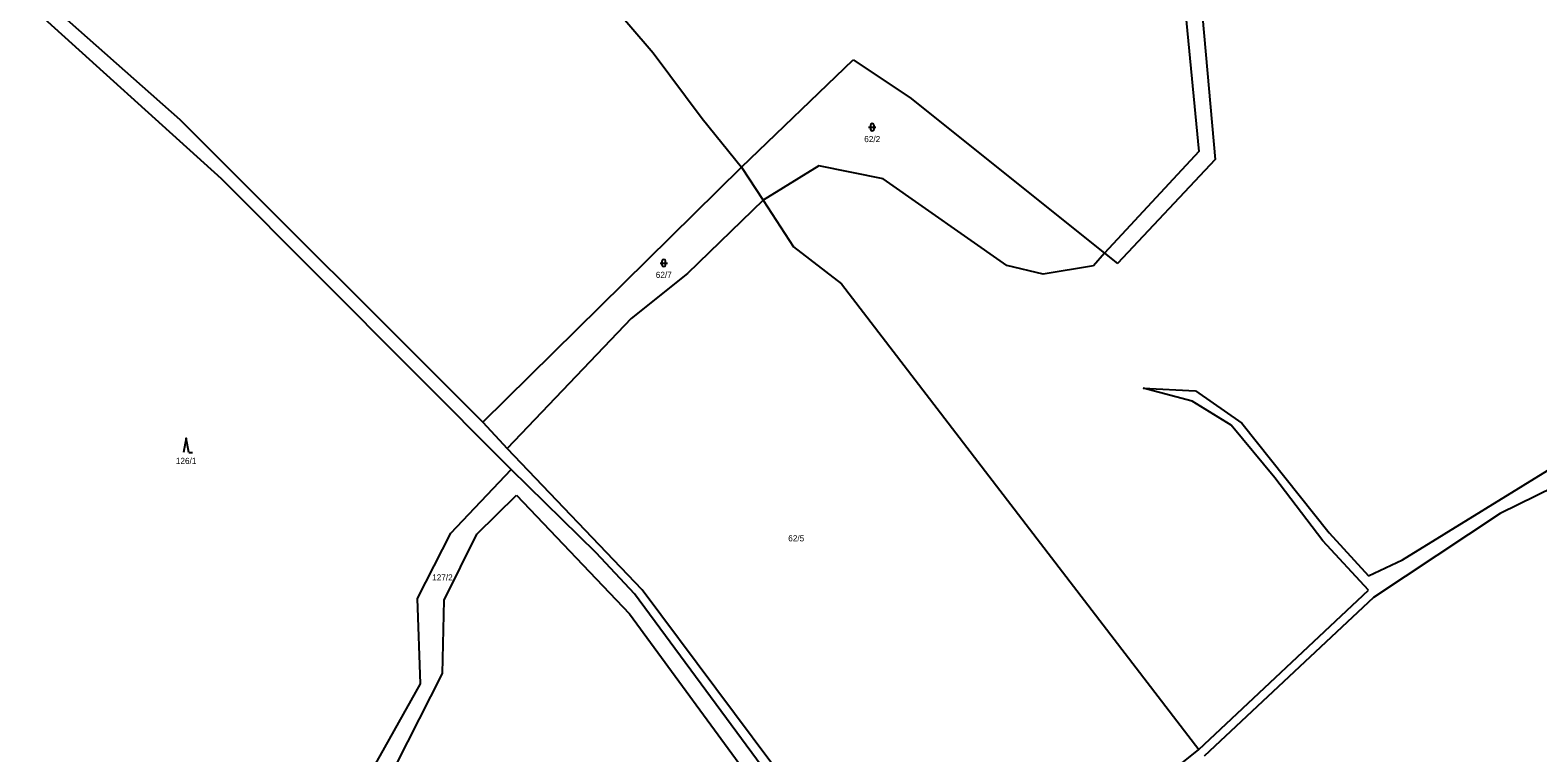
# Model space of a CAD drawing. Extents: x -601877 to -599786, y -1122905 to -1121218.
# Drawn here: x -600624.1 to -600206.4, y -1122172.1 to -1121972.1 of the extents above; entities that cross this region are included whole.
import ezdxf
from ezdxf.enums import TextEntityAlignment as Align

# ---------------------------------------------------------------- set-up
doc = ezdxf.new("R2010")
doc.units = 0
doc.header["$LTSCALE"] = 0.68
doc.layers.add('1', color=7, linetype='Continuous', lineweight=25)
doc.layers.add('3', color=7, linetype='Continuous', lineweight=25)
doc.layers.add('2', color=7, linetype='Continuous')

msp = doc.modelspace()

# ---------------------------------------------------------------- linework, layer by layer
at = {"layer": '1'}
for p, q in [((-600481.34, -1121943.53), (-600451.53, -1121978.39)), ((-600621.15, -1121962.72), (-600582.62, -1121996.8)), ((-600624.09, -1121965.36), (-600571.21, -1122013.14)), ((-600304.07, -1121967.38), (-600300.36, -1122005.74)), ((-600299.3, -1121968.61), (-600295.78, -1122007.91)), ((-600451.53, -1121978.39), (-600437.92, -1121996.56)), ((-600427, -1122010.05), (-600396.05, -1121980.36)), ((-600396.05, -1121980.36), (-600380.36, -1121990.79)), ((-600380.36, -1121990.79), (-600326.42, -1122033.8)), ((-600582.62, -1121996.8), (-600498.69, -1122080.61)), ((-600437.92, -1121996.56), (-600427, -1122010.05)), ((-600300.36, -1122005.74), (-600326.42, -1122033.8)), ((-600295.78, -1122007.91), (-600322.82, -1122036.66)), ((-600498.69, -1122080.61), (-600427, -1122010.05)), ((-600427, -1122010.05), (-600421.06, -1122019.14)), ((-600405.63, -1122009.69), (-600421.06, -1122019.14)), ((-600387.78, -1122013.29), (-600405.63, -1122009.69)), ((-600571.21, -1122013.14), (-600490.88, -1122093.71)), ((-600353.56, -1122037.22), (-600387.78, -1122013.29)), ((-600421.06, -1122019.14), (-600441.98, -1122039.43)), ((-600421.06, -1122019.14), (-600412.62, -1122032.05)), ((-600412.62, -1122032.05), (-600399.28, -1122042.29)), ((-600343.49, -1122039.68), (-600353.56, -1122037.22)), ((-600329.49, -1122037.3), (-600343.49, -1122039.68)), ((-600326.42, -1122033.8), (-600329.49, -1122037.3)), ((-600326.42, -1122033.8), (-600322.82, -1122036.66)), ((-600441.98, -1122039.43), (-600457.62, -1122051.88)), ((-600399.28, -1122042.29), (-600300.33, -1122171.21)), ((-600457.62, -1122051.88), (-600491.92, -1122087.9)), ((-600302.16, -1122074.84), (-600315.76, -1122071.21)), ((-600315.76, -1122071.21), (-600301.24, -1122071.92)), ((-600291.38, -1122081.42), (-600302.16, -1122074.84)), ((-600301.24, -1122071.92), (-600288.45, -1122080.88)), ((-600498.69, -1122080.61), (-600491.92, -1122087.9)), ((-600279.32, -1122096.05), (-600291.38, -1122081.42)), ((-600288.45, -1122080.88), (-600264.24, -1122111.23)), ((-600454.5, -1122127.05), (-600491.92, -1122087.9)), ((-600179.54, -1122087.46), (-600216.82, -1122105.93)), ((-600243.87, -1122118.73), (-600198.91, -1122091.02)), ((-600507.55, -1122111.3), (-600490.88, -1122093.71)), ((-600467.31, -1122116.76), (-600490.88, -1122093.71)), ((-600265.98, -1122113.42), (-600279.32, -1122096.05)), ((-600500.31, -1122111.64), (-600489.36, -1122100.86)), ((-600489.36, -1122100.86), (-600458.01, -1122133.71)), ((-600216.82, -1122105.93), (-600251.91, -1122129.15)), ((-600516.77, -1122129.4), (-600507.55, -1122111.3)), ((-600509.38, -1122129.86), (-600500.31, -1122111.64)), ((-600264.24, -1122111.23), (-600253.37, -1122123.12)), ((-600456.69, -1122128.15), (-600467.31, -1122116.76)), ((-600253.37, -1122127.14), (-600265.98, -1122113.42)), ((-600253.37, -1122123.12), (-600243.87, -1122118.73)), ((-600515.95, -1122153.01), (-600516.77, -1122129.4)), ((-600381.02, -1122230.51), (-600456.69, -1122128.15)), ((-600383.11, -1122222.48), (-600454.5, -1122127.05)), ((-600300.33, -1122171.21), (-600253.37, -1122127.14)), ((-600251.91, -1122129.15), (-600298.87, -1122173.08)), ((-600509.82, -1122150.16), (-600509.38, -1122129.86)), ((-600458.01, -1122133.71), (-600382.29, -1122237.02)), ((-600527.06, -1122183.95), (-600509.82, -1122150.16)), ((-600530.53, -1122179.04), (-600515.95, -1122153.01)), ((-600376.84, -1122232.39), (-600300.33, -1122171.21))]:
    msp.add_line(p, q, dxfattribs=at)
at = {"layer": '3'}
for p, q in [((-600391.811, -1121998.981), (-600389.809, -1121998.981)), ((-600391.311, -1121998.481), (-600391.311, -1121999.482)), ((-600390.309, -1121999.482), (-600390.309, -1121998.481)), ((-600449.561, -1122036.571), (-600447.559, -1122036.571)), ((-600449.061, -1122036.071), (-600449.061, -1122037.072)), ((-600448.059, -1122037.072), (-600448.059, -1122036.071)), ((-600580.13, -1122089.06), (-600579.134, -1122089.06))]:
    msp.add_line(p, q, dxfattribs=at)
msp.add_lwpolyline([(-600580.13, -1122089.06), (-600580.88, -1122085.06), (-600581.63, -1122089.06)], dxfattribs=at)
for centre, start, end in [((-600390.81, -1121998.4809), 0, 180), ((-600390.81, -1121999.4809), 180, 359.98789), ((-600448.56, -1122036.0709), 0, 180), ((-600448.56, -1122037.0709), 180, 359.98789)]:
    msp.add_arc(centre, 0.5, start, end, dxfattribs=at)

# ---------------------------------------------------------------- texts
at = {"layer": '2'}
for s, p in [('62/2', (-600390.809, -1122003.105)), ('62/7', (-600448.559, -1122040.695)), ('126/1', (-600580.88, -1122092.185)), ('62/5', (-600411.869, -1122113.605)), ('127/2', (-600509.87, -1122124.445))]:
    msp.add_text(s, height=1.7, dxfattribs=at).set_placement(p, align=Align.CENTER)

doc.saveas('drawing.dxf')
